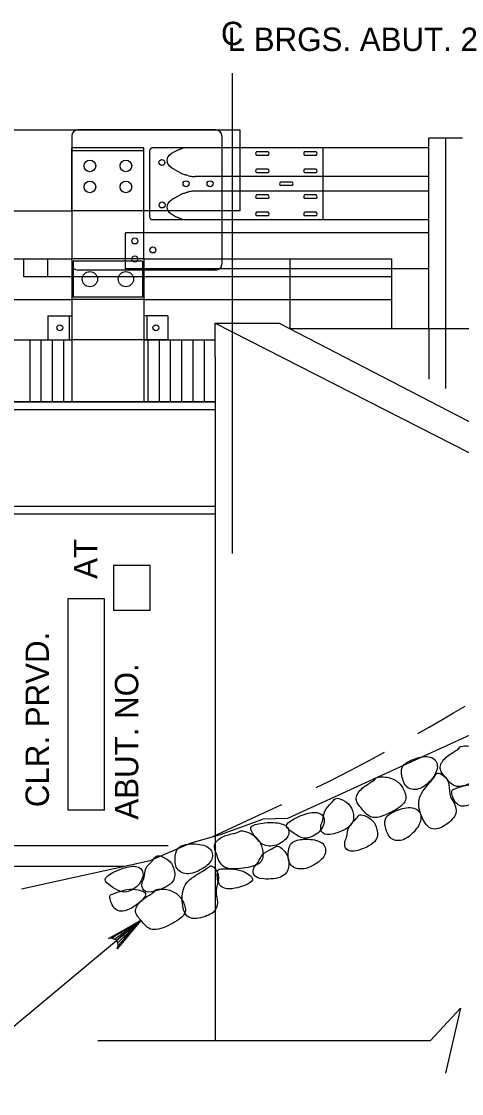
# Model space of a CAD drawing. Extents: x 638175 to 640495, y 294277 to 298435.
# Drawn here: x 638723.7 to 638780.2, y 297984.6 to 298122.2 of the extents above; entities that cross this region are included whole.
import ezdxf

# ---------------------------------------------------------------- set-up
doc = ezdxf.new("R2010")
doc.units = 0
for name, color, linetype in [('2', 7, 'Continuous'), ('3', 7, 'Continuous'), ('4', 7, 'Continuous'), ('5', 7, 'Continuous'), ('8', 7, 'Continuous'), ('Level 25', 7, 'Continuous')]:
    doc.layers.add(name, color=color, linetype=linetype)

msp = doc.modelspace()

# ---------------------------------------------------------------- linework, layer by layer
at = {"layer": '2'}
for p, q in [((638578.73, 298108.3), (638751.73, 298108.3)), ((638730.18, 298107.53), (638730.18, 298105.99)), ((638748.66, 298108.3), (638730.95, 298108.3)), ((638749.43, 298107.53), (638749.43, 298105.99)), ((638751.73, 298108.3), (638751.73, 298105.99)), ((638739.42, 298105.99), (638730.18, 298105.99)), ((638730.18, 298097.91), (638730.18, 298105.99)), ((638739.42, 298091.74), (638739.42, 298105.99)), ((638751.73, 298106), (638740.52, 298106)), ((638749.43, 298105.99), (638749.43, 298096.76)), ((638762.32, 298106), (638751.73, 298106)), ((638751.73, 298105.99), (638751.73, 298097.91)), ((638762.39, 298106), (638762.39, 298096.76)), ((638775.96, 298106), (638762.39, 298106)), ((638739.42, 298105.61), (638730.18, 298105.61)), ((638740.15, 298105.63), (638740.15, 298097.13)), ((638755.34, 298105.49), (638753.86, 298105.49)), ((638755.34, 298105.03), (638753.86, 298105.03)), ((638761.52, 298105.49), (638760.04, 298105.49)), ((638761.52, 298105.03), (638760.04, 298105.03)), ((638755.34, 298103.28), (638753.86, 298103.28)), ((638761.52, 298103.28), (638760.04, 298103.28)), ((638751.73, 298102.31), (638745.98, 298102.31)), ((638775.96, 298102.31), (638751.73, 298102.31)), ((638755.34, 298102.81), (638753.86, 298102.81)), ((638761.52, 298102.81), (638760.04, 298102.81)), ((638751.73, 298100.46), (638745.98, 298100.46)), ((638775.96, 298100.46), (638751.73, 298100.46)), ((638758.43, 298101.61), (638756.96, 298101.61)), ((638758.43, 298101.15), (638756.96, 298101.15)), ((638755.34, 298099.95), (638753.86, 298099.95)), ((638755.34, 298099.49), (638753.86, 298099.49)), ((638761.52, 298099.95), (638760.04, 298099.95)), ((638761.52, 298099.49), (638760.04, 298099.49)), ((638691.8, 298097.91), (638730.18, 298097.91)), ((638730.18, 298097.91), (638730.18, 298091.74)), ((638739.42, 298097.91), (638730.18, 298097.91)), ((638749.42, 298097.91), (638739.42, 298097.91)), ((638751.73, 298097.91), (638749.42, 298097.91)), ((638755.34, 298097.73), (638753.86, 298097.73)), ((638761.52, 298097.73), (638760.04, 298097.73)), ((638749.43, 298096.76), (638740.52, 298096.76)), ((638775.96, 298096.76), (638749.43, 298096.76)), ((638755.34, 298097.27), (638753.86, 298097.27)), ((638761.52, 298097.27), (638760.04, 298097.27)), ((638737.07, 298090.48), (638737.07, 298095.1)), ((638749.43, 298095.1), (638737.07, 298095.1)), ((638775.96, 298095.1), (638749.43, 298095.1)), ((638691.8, 298091.74), (638730.18, 298091.74)), ((638724.01, 298089.44), (638724.01, 298091.74)), ((638727.1, 298089.44), (638727.1, 298091.74)), ((638730.18, 298091.74), (638730.18, 298073.42)), ((638739.42, 298091.74), (638730.18, 298091.74)), ((638739.25, 298091.46), (638730.37, 298091.46)), ((638730.37, 298091.46), (638730.37, 298086.85)), ((638739.25, 298091.46), (638739.25, 298086.85)), ((638739.42, 298091.74), (638739.42, 298073.42)), ((638739.42, 298091.74), (638771.18, 298091.74)), ((638749.43, 298091.74), (638749.43, 298091.08)), ((638771.18, 298091.74), (638771.18, 298082.8)), ((638771.16, 298089.44), (638724.01, 298089.44)), ((638748.66, 298090.31), (638730.95, 298090.31)), ((638771.16, 298090.48), (638737.07, 298090.48)), ((638775.96, 298090.48), (638771.16, 298090.48)), ((638739.25, 298086.85), (638730.37, 298086.85)), ((638691.8, 298086.55), (638730.18, 298086.55)), ((638739.42, 298086.55), (638730.18, 298086.55)), ((638727.09, 298084.45), (638730.18, 298084.45)), ((638727.09, 298084.45), (638727.09, 298081.36)), ((638729.82, 298084.45), (638729.82, 298081.36)), ((638730.18, 298084.45), (638730.18, 298081.36)), ((638742.51, 298084.45), (638739.42, 298084.45)), ((638739.42, 298084.45), (638739.42, 298081.36)), ((638739.78, 298084.45), (638739.78, 298081.36)), ((638742.51, 298084.45), (638742.51, 298081.36)), ((638727.09, 298081.36), (638730.18, 298081.36)), ((638739.42, 298081.36), (638730.18, 298081.36)), ((638742.51, 298081.36), (638739.42, 298081.36))]:
    msp.add_line(p, q, dxfattribs=at)
for centre, radius in [((638741.73, 298104.12), 0.385), ((638732.49, 298103.68), 0.748), ((638737.11, 298103.68), 0.748), ((638732.49, 298100.99), 0.748), ((638737.11, 298100.99), 0.748), ((638744.83, 298101.39), 0.385), ((638747.91, 298101.39), 0.385), ((638741.76, 298098.67), 0.385), ((638738.26, 298094.05), 0.385), ((638738.26, 298091.74), 0.385), ((638740.57, 298092.89), 0.385), ((638732.5, 298089.15), 0.978), ((638737.11, 298089.15), 0.978), ((638728.64, 298082.9), 0.385), ((638740.96, 298082.9), 0.385)]:
    msp.add_circle(centre, radius, dxfattribs=at)
for centre, radius, start, end in [((638730.95, 298107.53), 0.77, 90, 180), ((638748.66, 298107.53), 0.77, 0, 90), ((638740.52, 298105.63), 0.369, 90, 180), ((638768.38, 298045.83), 64.73, 111.9093, 112.3149), ((638744.93, 298104.13), 1.88, 108.4934, 111.9093), ((638747.56, 298096.28), 10.17, 107.0234, 108.4934), ((638743.29, 298104.37), 0.916, 120.3532, 238.6149), ((638745.61, 298101.73), 4.42, 125.3229, 129.0151), ((638743.61, 298104.55), 0.955, 117.3798, 125.3229), ((638757.79, 298077.16), 31.8, 116.5749, 117.3798), ((638744.65, 298103.44), 2.42, 113.6547, 116.5749), ((638746.06, 298100.22), 5.93, 112.3149, 113.6547), ((638754, 298105.26), 0.269, 120.8559, 239.1441), ((638755.2, 298105.26), 0.269, 300.8559, 59.1441), ((638760.18, 298105.26), 0.269, 120.8559, 239.1441), ((638761.38, 298105.26), 0.269, 300.8559, 59.1441), ((638746.04, 298107.33), 4.94, 229.2007, 233.1182), ((638743.73, 298104.25), 1.09, 233.1182, 241.475), ((638930.8, 298448.44), 392.83, 241.475, 241.5275), ((638683.28, 297992.04), 126.36, 61.435, 61.5275), ((638754, 298103.05), 0.269, 120.8559, 239.1441), ((638755.2, 298103.05), 0.269, 300.8559, 59.1441), ((638760.18, 298103.05), 0.269, 120.8559, 239.1441), ((638761.38, 298103.05), 0.269, 300.8559, 59.1441), ((638688.68, 298001.95), 115.08, 61.2499, 61.435), ((638754.35, 298121.65), 21.45, 241.2499, 241.6785), ((638744.48, 298103.33), 0.644, 241.6785, 249.7671), ((638750.54, 298119.78), 18.18, 249.7671, 251.2889), ((638745.72, 298105.55), 3.14, 251.2889, 252.6389), ((638772.22, 298190.32), 91.96, 252.6389, 252.8885), ((638745.8, 298104.49), 2.16, 252.8885, 261.633), ((638746.22, 298107.33), 5.03, 261.633, 267.3571), ((638772.22, 298012.45), 91.96, 107.1115, 107.3611), ((638745.8, 298098.28), 2.16, 98.367, 107.1115), ((638746.22, 298095.43), 5.03, 92.6429, 98.367), ((638757.1, 298101.38), 0.269, 120.8559, 239.1441), ((638758.3, 298101.38), 0.269, 300.8559, 59.1441), ((638743.29, 298098.4), 0.916, 121.3851, 239.6468), ((638746.04, 298095.44), 4.94, 126.8818, 130.7993), ((638743.73, 298098.52), 1.09, 118.525, 126.8818), ((638930.8, 297754.33), 392.83, 118.4725, 118.525), ((638683.28, 298210.72), 126.36, 298.4725, 298.565), ((638688.68, 298200.82), 115.08, 298.565, 298.7501), ((638754.35, 298081.11), 21.45, 118.3215, 118.7501), ((638744.48, 298099.43), 0.644, 110.2329, 118.3215), ((638750.54, 298082.98), 18.18, 108.7111, 110.2329), ((638745.72, 298097.22), 3.14, 107.3611, 108.7111), ((638754, 298099.72), 0.269, 120.8559, 239.1441), ((638755.2, 298099.72), 0.269, 300.8559, 59.1441), ((638760.18, 298099.72), 0.269, 120.8559, 239.1441), ((638761.38, 298099.72), 0.269, 300.8559, 59.1441), ((638745.61, 298101.04), 4.42, 230.9849, 234.6771), ((638754, 298097.5), 0.269, 120.8559, 239.1441), ((638755.2, 298097.5), 0.269, 300.8559, 59.1441), ((638760.18, 298097.5), 0.269, 120.8559, 239.1441), ((638761.38, 298097.5), 0.269, 300.8559, 59.1441), ((638740.52, 298097.13), 0.369, 180, 270), ((638743.61, 298098.21), 0.955, 234.6771, 242.6202), ((638757.79, 298125.6), 31.8, 242.6202, 243.4251), ((638744.65, 298099.32), 2.42, 243.4251, 246.3453), ((638746.06, 298102.54), 5.93, 246.3453, 247.6851), ((638768.38, 298156.93), 64.73, 247.6851, 248.0907), ((638744.93, 298098.63), 1.88, 248.0907, 251.5066), ((638747.56, 298106.49), 10.17, 251.5066, 252.9766), ((638730.95, 298091.08), 0.77, 180, 270), ((638748.66, 298091.08), 0.77, 270, 0)]:
    msp.add_arc(centre, radius, start, end, dxfattribs=at)
at = {"layer": '3'}
for p, q in [((638775.96, 298107.27), (638780.28, 298107.27)), ((638775.96, 298082.8), (638775.96, 298107.27)), ((638778.12, 298107.27), (638778.12, 298075.1)), ((638758.17, 298082.8), (638758.17, 298091.74)), ((638739.42, 298086.55), (638771.18, 298086.55)), ((638748.57, 298083.52), (638814.78, 298049.64)), ((638748.57, 298079.19), (638748.57, 298083.52)), ((638748.57, 298083.52), (638756.5, 298083.52)), ((638748.57, 298079.19), (638748.57, 298083.52)), ((638748.57, 298083.52), (638756.79, 298083.52)), ((638756.79, 298083.52), (638821.91, 298049.64)), ((638758.17, 298082.8), (638823.72, 298082.8)), ((638758.17, 298082.8), (638823.72, 298082.8)), ((638775.96, 298082.8), (638775.96, 298076.31)), ((638691.8, 298081.36), (638730.18, 298081.36)), ((638739.42, 298081.36), (638748.57, 298081.36)), ((638748.57, 298079.19), (638748.57, 298017.69)), ((638569.79, 298073.43), (638748.57, 298073.43)), ((638569.79, 298073.43), (638748.57, 298073.43)), ((638569.79, 298073.42), (638748.57, 298073.42)), ((638569.79, 298072.43), (638748.57, 298072.43)), ((638569.79, 298060.01), (638748.57, 298060.01)), ((638569.79, 298059.01), (638748.57, 298059.01)), ((638789.43, 298034.4), (638757.84, 298019.92)), ((638757.84, 298019.92), (638754.69, 298019.84)), ((638748.57, 298017.69), (638748.57, 297991.42)), ((638576.14, 298013.81), (638736.87, 298013.81)), ((638776.18, 297991.42), (638780.03, 297995.59)), ((638780.03, 297995.59), (638778.1, 297987.24)), ((638733.5, 297991.42), (638776.18, 297991.42))]:
    msp.add_line(p, q, dxfattribs=at)
for points in [[(638779.88, 298029.01), (638779.83, 298028.93), (638779.49, 298028.64), (638777.91, 298027.73), (638777.11, 298026.29), (638778.12, 298025.24), (638779.32, 298023.61), (638781.9, 298024.62), (638784.12, 298026.03), (638783.57, 298027.63), (638782.78, 298028.75), (638781.18, 298029.36), (638779.83, 298029.15), (638779.94, 298029.1), (638779.88, 298029.01)], [(638772.66, 298026.67), (638772.38, 298026.3), (638772.41, 298025.47), (638773.04, 298023.64), (638774.88, 298023.5), (638776.63, 298025.13), (638777.33, 298026.76), (638776.36, 298028.1), (638774.09, 298027.69), (638772.93, 298027.04), (638772.66, 298026.67)], [(638769.11, 298025.03), (638769.05, 298024.95), (638768.72, 298024.66), (638767.13, 298023.74), (638766.34, 298022.31), (638767.34, 298021.26), (638768.54, 298019.63), (638771.12, 298020.63), (638773.34, 298022.05), (638772.79, 298023.64), (638772.01, 298024.77), (638770.4, 298025.38), (638769.06, 298025.17), (638769.16, 298025.12), (638769.11, 298025.03)], [(638776.98, 298025.71), (638776.84, 298025.62), (638776.73, 298025.16), (638774.46, 298022.85), (638774.71, 298020.64), (638776.11, 298018.05), (638778.31, 298019.06), (638779.72, 298020.57), (638779.25, 298021.94), (638778.5, 298022.96), (638778.64, 298024.8), (638777.56, 298025.7), (638777.11, 298025.8), (638776.98, 298025.71)], [(638779.43, 298023.79), (638779.01, 298023.64), (638778.7, 298023.54), (638779.41, 298021.48), (638781.13, 298021.31), (638784.25, 298023.77), (638782.41, 298024.3), (638781.22, 298024.4), (638779.84, 298023.93), (638779.43, 298023.79)], [(638762.39, 298019.78), (638762.32, 298019.48), (638762.02, 298019.11), (638762.17, 298017.89), (638763.52, 298017.72), (638766.41, 298018.97), (638766.32, 298020.72), (638765.81, 298021.82), (638764.54, 298022.53), (638763.89, 298022.56), (638763.59, 298021.95), (638762.42, 298020.92), (638762.46, 298020.08), (638762.39, 298019.78)], [(638757.91, 298018.59), (638758.15, 298018.33), (638759.01, 298017.78), (638760.12, 298017.13), (638762.1, 298018.07), (638762.86, 298020), (638761.77, 298020.91), (638759.75, 298020.47), (638757.57, 298019.32), (638757.66, 298018.85), (638757.91, 298018.59)], [(638770.55, 298020.12), (638770.27, 298019.75), (638770.31, 298018.92), (638770.94, 298017.09), (638772.78, 298016.95), (638774.53, 298018.58), (638775.23, 298020.21), (638774.26, 298021.55), (638771.98, 298021.14), (638770.83, 298020.49), (638770.55, 298020.12)], [(638753.21, 298018.34), (638753.35, 298018.01), (638753.99, 298017.21), (638754.83, 298016.24), (638757.01, 298016.48), (638758.35, 298018.06), (638757.62, 298019.27), (638755.57, 298019.51), (638753.13, 298019.14), (638753.06, 298018.66), (638753.21, 298018.34)], [(638765.46, 298017.66), (638765.39, 298017.36), (638765.09, 298016.99), (638765.24, 298015.77), (638766.58, 298015.6), (638769.48, 298016.85), (638769.38, 298018.61), (638768.87, 298019.71), (638767.61, 298020.41), (638766.96, 298020.44), (638766.66, 298019.83), (638765.49, 298018.8), (638765.52, 298017.96), (638765.46, 298017.66)], [(638751.69, 298018.27), (638751.61, 298018.2), (638751.21, 298018.04), (638749.41, 298017.69), (638748.19, 298016.59), (638748.8, 298015.28), (638749.41, 298013.34), (638752.17, 298013.46), (638754.73, 298014.07), (638754.73, 298015.76), (638754.35, 298017.08), (638753.03, 298018.17), (638751.69, 298018.42), (638751.77, 298018.33), (638751.69, 298018.27)], [(638744.01, 298016.28), (638743.62, 298016.02), (638743.39, 298015.22), (638743.39, 298013.29), (638745.09, 298012.56), (638747.27, 298013.53), (638748.46, 298014.85), (638747.98, 298016.43), (638745.69, 298016.78), (638744.39, 298016.54), (638744.01, 298016.28)], [(638754.08, 298014.34), (638753.92, 298014.07), (638753.51, 298013.83), (638753.26, 298012.62), (638754.47, 298012.02), (638757.62, 298012.27), (638758.1, 298013.96), (638757.97, 298015.16), (638757.01, 298016.24), (638756.4, 298016.48), (638755.92, 298016), (638754.47, 298015.41), (638754.24, 298014.6), (638754.08, 298014.34)], [(638758.52, 298016.89), (638758.14, 298016.63), (638757.9, 298015.83), (638757.9, 298013.89), (638759.6, 298013.17), (638761.78, 298014.13), (638762.97, 298015.46), (638762.49, 298017.03), (638760.21, 298017.39), (638758.91, 298017.15), (638758.52, 298016.89)], [(638739.46, 298012.41), (638739.39, 298012.11), (638739.09, 298011.74), (638739.24, 298010.52), (638740.58, 298010.35), (638743.48, 298011.6), (638743.38, 298013.35), (638742.87, 298014.46), (638741.61, 298015.16), (638740.96, 298015.19), (638740.66, 298014.58), (638739.48, 298013.55), (638739.52, 298012.71), (638739.46, 298012.41)], [(638734.66, 298011.68), (638734.9, 298011.42), (638735.76, 298010.87), (638736.87, 298010.23), (638738.85, 298011.16), (638739.61, 298013.09), (638738.52, 298013.99), (638736.5, 298013.56), (638734.32, 298012.42), (638734.41, 298011.94), (638734.66, 298011.68)], [(638747.96, 298013.84), (638747.8, 298013.8), (638747.54, 298013.4), (638744.65, 298011.95), (638744.17, 298009.78), (638744.65, 298006.88), (638747.06, 298007.12), (638748.88, 298008.09), (638748.88, 298009.53), (638748.51, 298010.74), (638749.24, 298012.43), (638748.51, 298013.64), (638748.12, 298013.88), (638747.96, 298013.84)], [(638749.56, 298013.47), (638749.12, 298013.47), (638748.8, 298013.47), (638748.8, 298011.3), (638750.37, 298010.57), (638754.12, 298011.89), (638752.55, 298012.99), (638751.46, 298013.47), (638750.01, 298013.47), (638749.56, 298013.47)], [(638735.6, 298010.31), (638735.18, 298010.17), (638734.87, 298010.07), (638735.58, 298008.01), (638737.3, 298007.83), (638740.42, 298010.3), (638738.58, 298010.83), (638737.39, 298010.93), (638736.02, 298010.46), (638735.6, 298010.31)], [(638740.83, 298010.64), (638740.77, 298010.55), (638740.44, 298010.27), (638738.86, 298009.35), (638738.06, 298007.92), (638739.07, 298006.87), (638740.27, 298005.24), (638742.84, 298006.24), (638745.07, 298007.65), (638744.52, 298009.25), (638743.73, 298010.37), (638742.13, 298010.98), (638740.78, 298010.78), (638740.89, 298010.72), (638740.83, 298010.64)]]:
    msp.add_open_spline(points, degree=3, dxfattribs=at)
at = {"layer": '4'}
for p, q in [((638750.73, 298115.59), (638750.73, 298053.94)), ((638735.53, 298052.39), (638735.53, 298046.64)), ((638740.23, 298052.39), (638735.53, 298052.39)), ((638740.23, 298046.64), (638740.23, 298052.39)), ((638729.68, 298048.13), (638729.68, 298020.99)), ((638734.39, 298048.13), (638729.68, 298048.13)), ((638734.39, 298020.99), (638734.39, 298048.13)), ((638740.23, 298046.64), (638735.53, 298046.64)), ((638734.39, 298020.99), (638729.68, 298020.99)), ((638711.69, 298016.44), (638742.52, 298016.44)), ((638739.03, 298006.85), (638712.39, 297984.62))]:
    msp.add_line(p, q, dxfattribs=at)
for points in [[(638723.72, 298010.89), (638740.24, 298014.55), (638745.49, 298016.8), (638749.26, 298017.89), (638754.69, 298019.84)], [(638739.03, 298006.85), (638736.01, 298003.19), (638736.13, 298003.62), (638736.07, 298003.97), (638735.91, 298004.25), (638735.67, 298004.46), (638735.33, 298004.58), (638734.89, 298004.54), (638739.03, 298006.85), (638735.33, 298004.58), (638735.67, 298004.46), (638739.03, 298006.85), (638735.91, 298004.25), (638736.07, 298003.97), (638739.03, 298006.85), (638736.13, 298003.62)]]:
    msp.add_lwpolyline(points, dxfattribs=at)
msp.add_lwpolyline([(638736.45, 298005.34), (638737.08, 298004.58), (638739.03, 298006.85)], close=True, dxfattribs=at)
at = {"layer": '5'}
for p, q in [((638724.78, 298081.36), (638724.78, 298073.43)), ((638724.78, 298081.36), (638724.78, 298073.42)), ((638726.22, 298081.36), (638726.22, 298073.42)), ((638727.66, 298081.36), (638727.66, 298073.42)), ((638729.1, 298081.36), (638729.1, 298073.42)), ((638739.92, 298081.36), (638739.92, 298073.43)), ((638739.92, 298081.36), (638739.92, 298073.42)), ((638741.36, 298081.36), (638741.36, 298073.43)), ((638741.36, 298081.36), (638741.36, 298073.42)), ((638742.81, 298081.36), (638742.81, 298073.43)), ((638742.81, 298081.36), (638742.81, 298073.42)), ((638744.25, 298081.36), (638744.25, 298073.43)), ((638744.25, 298081.36), (638744.25, 298073.42)), ((638745.69, 298081.36), (638745.69, 298073.43)), ((638745.69, 298081.36), (638745.69, 298073.42)), ((638747.13, 298081.36), (638747.13, 298073.43)), ((638747.13, 298081.36), (638747.13, 298073.42))]:
    msp.add_line(p, q, dxfattribs=at)
at = {"layer": '8'}
for p, q in [((638779.14, 298033.48), (638780.63, 298034.36)), ((638777.61, 298032.58), (638779.14, 298033.48)), ((638774.56, 298030.82), (638776.01, 298031.65)), ((638776.01, 298031.65), (638777.61, 298032.58)), ((638768.32, 298027.37), (638770.26, 298028.42)), ((638763.12, 298024.69), (638765.87, 298026.09)), ((638765.87, 298026.09), (638768.32, 298027.37)), ((638761.52, 298023.89), (638763.12, 298024.69)), ((638752.6, 298019.61), (638756.54, 298021.46)), ((638756.54, 298021.46), (638757.1, 298021.73)), ((638748.17, 298017.58), (638752.6, 298019.61))]:
    msp.add_line(p, q, dxfattribs=at)
at = {"layer": 'Level 25'}
for p, q in [((638730.18, 298105.99), (638730.18, 298091.08)), ((638749.43, 298096.76), (638749.43, 298091.74))]:
    msp.add_line(p, q, dxfattribs=at)

# ---------------------------------------------------------------- texts
at = {"layer": '4'}
for s, p in [('C', (638749.3, 298119.18)), ('L BRGS. ABUT. 2', (638750.16, 298118.43))]:
    msp.add_text(s, height=3, dxfattribs=at).set_placement(p)
for s, p in [('AT', (638733.44, 298050.68)), ('CLR. PRVD.', (638727.24, 298021.38)), ('ABUT. NO. ', (638738.7, 298019.78))]:
    msp.add_text(s, height=3, rotation=90, dxfattribs=at).set_placement(p)

doc.saveas('drawing.dxf')
